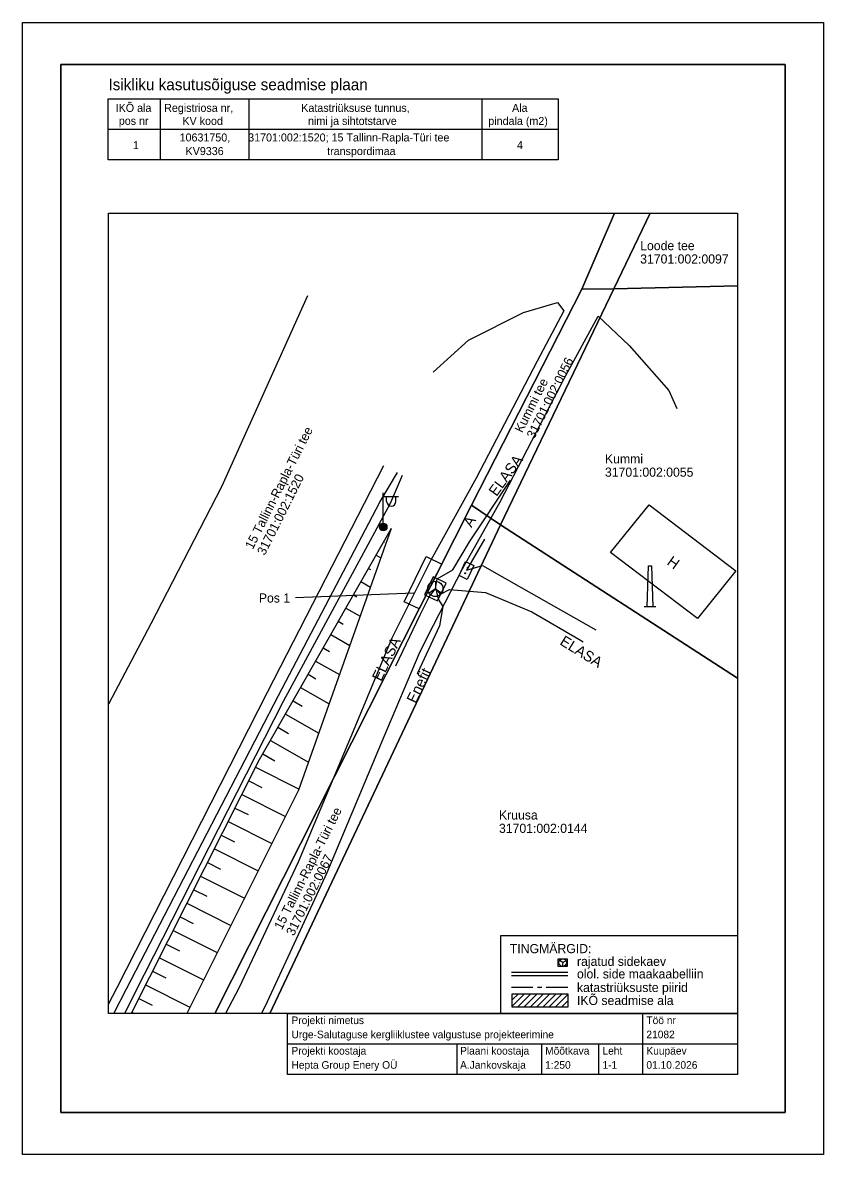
# Model space of a CAD drawing. Extents: x 544715.2 to 544767.7, y 6560571.5 to 6560645.7.
import ezdxf

# ---------------------------------------------------------------- set-up
doc = ezdxf.new("R2010")
doc.units = 0
for name, color, linetype in [('AED', 7, 'Continuous'), ('HOONE', 7, 'Continuous'), ('KASUTUSALA', 7, 'Continuous'), ('PIIR', 7, 'Continuous'), ('POST', 7, 'Continuous'), ('PR_SIDE', 7, 'Continuous'), ('RAJATIS', 7, 'Continuous'), ('RELJEEF', 7, 'Continuous'), ('SITRASS', 7, 'Continuous'), ('TEE', 7, 'Continuous'), ('VORMISTUS', 7, 'Continuous')]:
    doc.layers.add(name, color=color, linetype=linetype)

msp = doc.modelspace()

# ---------------------------------------------------------------- linework, layer by layer
at = {"layer": 'AED'}
msp.add_lwpolyline([(544721.237, 6560580.719), (544722.058, 6560582.33), (544732.034, 6560601.578), (544738.658, 6560614.261), (544739.83, 6560616.203)], dxfattribs=at)
at = {"layer": 'HOONE'}
msp.add_lwpolyline([(544762.012, 6560609.749), (544759.49, 6560606.615), (544753.802, 6560610.946), (544756.324, 6560614.08), (544762.012, 6560609.749)], dxfattribs=at)
at = {"layer": 'KASUTUSALA'}
msp.add_lwpolyline([(544742.724, 6560610.196), (544741.237, 6560607.25), (544740.271, 6560607.715), (544741.702, 6560610.688)], close=True, dxfattribs=at)
at = {"layer": 'PIIR'}
for points in [[(544727.845, 6560580.719), (544744.68, 6560614.07), (544751.91, 6560628.23), (544754.05, 6560633.219)], [(544754.05, 6560633.219), (544751.91, 6560628.23), (544754.02, 6560628.26), (544756.396, 6560633.219)], [(544756.396, 6560633.219), (544754.02, 6560628.26), (544762.123, 6560628.454)], [(544762.123, 6560628.454), (544754.02, 6560628.26), (544746.58, 6560612.78), (544762.123, 6560602.717)], [(544731.446, 6560580.719), (544746.58, 6560612.78), (544744.68, 6560614.07), (544727.845, 6560580.719)], [(544762.123, 6560602.717), (544746.58, 6560612.78), (544731.446, 6560580.719)]]:
    msp.add_lwpolyline(points, dxfattribs=at)
msp.add_lwpolyline([(544751.91, 6560628.23), (544744.68, 6560614.07), (544746.58, 6560612.78), (544754.02, 6560628.26)], close=True, dxfattribs=at)
at = {"layer": 'POST'}
for p, q in [((544738.887, 6560612.878), (544738.887, 6560614.878)), ((544738.887, 6560612.878), (544738.887, 6560614.878)), ((544738.887, 6560614.628), (544739.887, 6560614.628)), ((544738.887, 6560614.628), (544739.887, 6560614.628)), ((544739.114, 6560614.307), (544739.114, 6560614.628)), ((544739.114, 6560614.307), (544739.114, 6560614.628)), ((544739.727, 6560614.307), (544739.727, 6560614.628)), ((544739.727, 6560614.307), (544739.727, 6560614.628)), ((544738.887, 6560612.628), (544738.887, 6560612.628)), ((544738.887, 6560612.628), (544738.887, 6560612.628))]:
    msp.add_line(p, q, dxfattribs=at)
msp.add_lwpolyline([(544743.862, 6560609.452), (544744.292, 6560610.355), (544744.834, 6560610.096), (544744.403, 6560609.194)], close=True, dxfattribs=at)
for centre, radius in [((544738.887, 6560612.628), 0.25), ((544738.887, 6560612.628), 0.25), ((544738.887, 6560612.628), 0.225), ((544738.887, 6560612.628), 0.225), ((544738.887, 6560612.628), 0.2), ((544738.887, 6560612.628), 0.2), ((544738.887, 6560612.628), 0.175), ((544738.887, 6560612.628), 0.175), ((544738.887, 6560612.628), 0.15), ((544738.887, 6560612.628), 0.15), ((544738.887, 6560612.628), 0.125), ((544738.887, 6560612.628), 0.125), ((544738.887, 6560612.628), 0.1), ((544738.887, 6560612.628), 0.1), ((544738.887, 6560612.628), 0.075), ((544738.887, 6560612.628), 0.075), ((544738.887, 6560612.628), 0.05), ((544738.887, 6560612.628), 0.05), ((544738.887, 6560612.628), 0.025), ((544738.887, 6560612.628), 0.025), ((544744.434, 6560609.955), 0.0304), ((544744.434, 6560609.955), 0.029), ((544744.434, 6560609.955), 0.0277), ((544744.434, 6560609.955), 0.0263), ((544744.434, 6560609.955), 0.0249), ((544744.434, 6560609.955), 0.0236), ((544744.434, 6560609.955), 0.0222), ((544744.434, 6560609.955), 0.0209), ((544744.434, 6560609.955), 0.0195), ((544744.434, 6560609.955), 0.0181), ((544744.434, 6560609.955), 0.0168), ((544744.434, 6560609.955), 0.0154), ((544744.434, 6560609.955), 0.014), ((544744.434, 6560609.955), 0.0127), ((544744.434, 6560609.955), 0.0113), ((544744.434, 6560609.955), 0.00996), ((544744.434, 6560609.955), 0.0086), ((544744.434, 6560609.955), 0.00724), ((544744.434, 6560609.955), 0.00587), ((544744.434, 6560609.955), 0.00451), ((544744.434, 6560609.955), 0.00315), ((544744.434, 6560609.955), 0.00179), ((544744.434, 6560609.955), 0.000426), ((544744.261, 6560609.594), 0.0304), ((544744.261, 6560609.594), 0.029), ((544744.261, 6560609.594), 0.0277), ((544744.261, 6560609.594), 0.0263), ((544744.261, 6560609.594), 0.0249), ((544744.261, 6560609.594), 0.0236), ((544744.261, 6560609.594), 0.0222), ((544744.261, 6560609.594), 0.0209), ((544744.261, 6560609.594), 0.0195), ((544744.261, 6560609.594), 0.0181), ((544744.261, 6560609.594), 0.0168), ((544744.261, 6560609.594), 0.0154), ((544744.261, 6560609.594), 0.014), ((544744.261, 6560609.594), 0.0127), ((544744.261, 6560609.594), 0.0113), ((544744.261, 6560609.594), 0.00996), ((544744.261, 6560609.594), 0.0086), ((544744.261, 6560609.594), 0.00724), ((544744.261, 6560609.594), 0.00587), ((544744.261, 6560609.594), 0.00451), ((544744.261, 6560609.594), 0.00315), ((544744.261, 6560609.594), 0.00179), ((544744.261, 6560609.594), 0.000426)]:
    msp.add_circle(centre, radius, dxfattribs=at)
msp.add_arc((544739.42, 6560614.307), 0.306, 180, 0, dxfattribs=at)
msp.add_arc((544739.42, 6560614.307), 0.306, 180, 0, dxfattribs=at)
at = {"layer": 'PR_SIDE'}
for p, q in [((544742.307, 6560609.067), (544742.307, 6560608.567)), ((544742.307, 6560608.567), (544741.892, 6560608.292)), ((544742.307, 6560608.567), (544742.722, 6560608.292))]:
    msp.add_line(p, q, dxfattribs=at)
msp.add_lwpolyline([(544742.17, 6560609.354), (544741.606, 6560608.183), (544742.444, 6560607.779), (544743.008, 6560608.951)], close=True, dxfattribs=at)
msp.add_circle((544742.307, 6560608.567), 0.5, dxfattribs=at)
at = {"layer": 'RAJATIS'}
for p, q in [((544756.289, 6560610.082), (544756.482, 6560610.082)), ((544756.482, 6560610.082), (544756.578, 6560607.387)), ((544756.771, 6560607.387), (544756.001, 6560607.387)), ((544756.578, 6560607.387), (544756.193, 6560607.387))]:
    msp.add_line(p, q, dxfattribs=at)
msp.add_lwpolyline([(544756.483, 6560610.082), (544756.578, 6560607.387), (544756.193, 6560607.387), (544756.288, 6560610.082)], close=True, dxfattribs=at)
at = {"layer": 'RELJEEF'}
for p, q in [((544739.408, 6560612.523), (544739.408, 6560612.523)), ((544738.913, 6560611.654), (544738.96, 6560611.627)), ((544738.418, 6560610.785), (544738.731, 6560610.607)), ((544737.923, 6560609.916), (544738.064, 6560609.836)), ((544737.428, 6560609.047), (544738.054, 6560608.691)), ((544736.933, 6560608.178), (544737.168, 6560608.045)), ((544736.438, 6560607.309), (544737.376, 6560606.775)), ((544735.943, 6560606.441), (544736.272, 6560606.254)), ((544735.448, 6560605.572), (544736.699, 6560604.859)), ((544734.953, 6560604.703), (544735.376, 6560604.462)), ((544734.459, 6560603.834), (544736.022, 6560602.943)), ((544733.964, 6560602.965), (544734.479, 6560602.671)), ((544733.469, 6560602.096), (544735.345, 6560601.027)), ((544732.974, 6560601.227), (544733.583, 6560600.88)), ((544732.479, 6560600.358), (544734.668, 6560599.111)), ((544731.984, 6560599.489), (544732.687, 6560599.088)), ((544731.489, 6560598.62), (544733.99, 6560597.195)), ((544730.994, 6560597.751), (544731.791, 6560597.297)), ((544730.523, 6560596.87), (544733.368, 6560595.434)), ((544730.072, 6560595.977), (544730.929, 6560595.545)), ((544729.621, 6560595.084), (544732.48, 6560593.642)), ((544729.171, 6560594.191), (544730.029, 6560593.758)), ((544728.72, 6560593.299), (544731.583, 6560591.854)), ((544728.27, 6560592.406), (544729.129, 6560591.972)), ((544727.819, 6560591.513), (544730.687, 6560590.066)), ((544727.369, 6560590.621), (544728.23, 6560590.186)), ((544726.918, 6560589.728), (544729.791, 6560588.278)), ((544726.467, 6560588.835), (544727.33, 6560588.4)), ((544726.017, 6560587.942), (544728.895, 6560586.49)), ((544725.566, 6560587.05), (544726.43, 6560586.613)), ((544725.116, 6560586.157), (544727.999, 6560584.702)), ((544724.665, 6560585.264), (544725.531, 6560584.827)), ((544724.214, 6560584.371), (544727.102, 6560582.914)), ((544723.764, 6560583.479), (544724.631, 6560583.041)), ((544723.313, 6560582.586), (544726.206, 6560581.126)), ((544722.863, 6560581.693), (544723.731, 6560581.255)), ((544722.412, 6560580.8), (544722.574, 6560580.719))]:
    msp.add_line(p, q, dxfattribs=at)
for points in [[(544739.408, 6560612.523), (544730.763, 6560597.346), (544722.371, 6560580.719)], [(544739.408, 6560612.523), (544733.343, 6560595.364), (544726.002, 6560580.719)]]:
    msp.add_lwpolyline(points, dxfattribs=at)
at = {"layer": 'SITRASS'}
for points in [[(544742.307, 6560608.567), (544742.434, 6560609.227), (544743.461, 6560609.821), (544744.546, 6560611.657), (544747.243, 6560615.692)], [(544745.52, 6560611.834), (544744.357, 6560609.803)], [(544744.357, 6560609.803), (544745.392, 6560610.113)], [(544745.392, 6560610.113), (544747.929, 6560608.662), (544752.831, 6560605.879)], [(544739.725, 6560603.511), (544741.31, 6560606.868), (544741.895, 6560608.043), (544742.307, 6560608.567)], [(544742.332, 6560608.578), (544742.496, 6560607.887), (544742.79, 6560607.42), (544742.588, 6560606.141), (544741.145, 6560603.047), (544741.116, 6560602.984)], [(544742.307, 6560608.567), (544742.653, 6560608.213), (544743.225, 6560608.535), (544745.595, 6560608.342), (544748.643, 6560607.071), (544751.717, 6560605.277), (544751.991, 6560605.105)]]:
    msp.add_lwpolyline(points, dxfattribs=at)
at = {"layer": 'TEE'}
for points in [[(544733.934, 6560627.793), (544728.292, 6560615.274), (544723.65, 6560606.272), (544720.873, 6560601)], [(544742.172, 6560622.797), (544744.481, 6560624.88), (544748.08, 6560626.694), (544750.321, 6560627.366), (544750.73, 6560626.821), (544748.985, 6560623.517), (544744.977, 6560615.832), (544742.015, 6560610.453), (544739.455, 6560605.333)], [(544741.302, 6560604.463), (544742.186, 6560606.186), (544744.086, 6560609.876), (544746.564, 6560614.282), (544750.732, 6560622.318), (544752.987, 6560626.468), (544755.012, 6560624.539), (544757.625, 6560621.575), (544758.142, 6560620.402)], [(544720.873, 6560581.313), (544721.449, 6560582.414), (544731.292, 6560601.787), (544738.927, 6560616.655)], [(544721.953, 6560580.719), (544722.619, 6560582.079), (544732.346, 6560601.2), (544739.356, 6560614.182), (544740.163, 6560616.037)], [(544739.455, 6560605.333), (544737.024, 6560599.505), (544733.309, 6560590.648), (544729.425, 6560582.362), (544728.556, 6560580.719)], [(544730.916, 6560580.719), (544731.178, 6560581.223), (544735.213, 6560589.953), (544738.884, 6560598.739), (544741.302, 6560604.463)]]:
    msp.add_lwpolyline(points, dxfattribs=at)
at = {"layer": 'VORMISTUS'}
for p, q in [((544724.259, 6560640.724), (544724.259, 6560636.724)), ((544730.084, 6560640.724), (544730.084, 6560636.724)), ((544745.359, 6560640.724), (544745.359, 6560636.724)), ((544720.859, 6560638.724), (544750.359, 6560638.724)), ((544740.906, 6560608.294), (544733.134, 6560607.973)), ((544750.658, 6560584.05), (544750.444, 6560584.178)), ((544750.658, 6560584.05), (544750.624, 6560583.804)), ((544750.884, 6560584.159), (544750.658, 6560584.05)), ((544747.298, 6560583.422), (544750.993, 6560583.422)), ((544747.298, 6560583.201), (544750.993, 6560583.201)), ((544748.708, 6560582.419), (544747.298, 6560582.419)), ((544749.291, 6560582.419), (544749, 6560582.419)), ((544750.993, 6560582.419), (544749.582, 6560582.419)), ((544748.162, 6560582.006), (544747.352, 6560581.196)), ((544747.75, 6560582.006), (544747.352, 6560581.608)), ((544748.573, 6560582.006), (544747.7, 6560581.132)), ((544748.985, 6560582.006), (544748.112, 6560581.132)), ((544749.397, 6560582.006), (544748.524, 6560581.132)), ((544749.809, 6560582.006), (544748.935, 6560581.132)), ((544750.221, 6560582.006), (544749.347, 6560581.132)), ((544750.633, 6560582.006), (544749.759, 6560581.132)), ((544750.993, 6560581.954), (544750.171, 6560581.132)), ((544750.993, 6560581.542), (544750.583, 6560581.132)), ((544755.896, 6560580.719), (544755.896, 6560578.719)), ((544732.623, 6560578.719), (544762.123, 6560578.719)), ((544743.716, 6560578.719), (544743.716, 6560576.719)), ((544749.259, 6560578.719), (544749.259, 6560576.719)), ((544753.012, 6560578.719), (544753.012, 6560576.719)), ((544755.896, 6560578.719), (544755.896, 6560576.719))]:
    msp.add_line(p, q, dxfattribs=at)
for points in [[(544715.248, 6560645.719), (544767.748, 6560645.719), (544767.748, 6560571.469), (544715.248, 6560571.469)], [(544717.748, 6560574.219), (544765.248, 6560574.219), (544765.248, 6560642.969), (544717.748, 6560642.969)], [(544717.748, 6560642.969), (544765.248, 6560642.969), (544765.248, 6560574.219), (544717.748, 6560574.219)], [(544720.859, 6560640.724), (544750.359, 6560640.724), (544750.359, 6560636.724), (544720.859, 6560636.724)], [(544762.123, 6560580.719), (544720.873, 6560580.719), (544720.873, 6560633.219), (544762.123, 6560633.219)], [(544746.593, 6560580.719), (544746.593, 6560585.819), (544762.123, 6560585.819), (544762.123, 6560580.719)], [(544750.983, 6560584.283), (544750.333, 6560584.283), (544750.333, 6560583.818), (544750.983, 6560583.818)], [(544747.352, 6560582.006), (544750.993, 6560582.006), (544750.993, 6560581.132), (544747.352, 6560581.132)], [(544732.623, 6560580.719), (544762.123, 6560580.719), (544762.123, 6560576.719), (544732.623, 6560576.719)]]:
    msp.add_lwpolyline(points, close=True, dxfattribs=at)
msp.add_circle((544750.658, 6560584.05), 0.25, dxfattribs=at)

# ---------------------------------------------------------------- texts
at = {"layer": 'HOONE'}
msp.add_text('H', height=0.7, rotation=324.36519, dxfattribs=at).set_placement((544757.439, 6560610.208))
at = {"layer": 'PIIR'}
for s, p in [('Loode tee', (544755.738, 6560630.788)), ('31701:002:0097', (544755.738, 6560629.913)), ('Kummi', (544753.428, 6560616.802)), ('31701:002:0055', (544753.428, 6560615.927)), ('Kruusa', (544746.479, 6560593.435)), ('31701:002:0144', (544746.479, 6560592.56))]:
    msp.add_text(s, height=0.6, dxfattribs=at).set_placement(p)
for s, rotation, p in [('31701:002:0056', 63.46115, (544748.794, 6560618.373)), ('Kummi tee', 63.46115, (544748.011, 6560618.764)), ('15 Tallinn-Rapla-Türi tee', 63.36779, (544730.337, 6560611.118)), ('31701:002:1520', 63.36779, (544731.12, 6560610.725)), ('15 Tallinn-Rapla-Türi tee', 63.43301, (544732.243, 6560586.153)), ('31701:002:0067', 63.43301, (544733.025, 6560585.761))]:
    msp.add_text(s, height=0.6, rotation=rotation, dxfattribs=at).set_placement(p)
at = {"layer": 'SITRASS'}
for s, rotation, p in [('ELASA', 53.97635, (544746.316, 6560614.593)), ('ELASA', 328.24149, (544750.414, 6560604.953)), ('ELASA', 64.23226, (544738.753, 6560602.459)), ('Enefit', 64.23226, (544741.022, 6560601.004))]:
    msp.add_text(s, height=0.7, rotation=rotation, dxfattribs=at).set_placement(p)
at = {"layer": 'TEE'}
msp.add_text('A', height=0.7, rotation=59.20555, dxfattribs=at).set_placement((544744.677, 6560612.548))
at = {"layer": 'VORMISTUS'}
for s, height, p in [('Isikliku kasutusõiguse seadmise plaan', 0.75, (544720.875, 6560641.286)), ('IKÕ ala', 0.525, (544721.348, 6560639.864)), ('Registriosa nr,', 0.525, (544724.527, 6560639.864)), ('Katastriüksuse tunnus,', 0.525, (544733.517, 6560639.864)), ('Ala', 0.525, (544747.338, 6560639.864)), ('pos nr', 0.525, (544721.553, 6560639.013)), ('KV kood', 0.525, (544725.724, 6560639.006)), ('nimi ja sihtotstarve', 0.525, (544733.962, 6560639.009)), ('pindala (m2)', 0.525, (544745.782, 6560639.006)), ('1', 0.525, (544722.484, 6560637.424)), ('10631750,', 0.525, (544725.539, 6560637.924)), ('31701:002:1520; 15 Tallinn-Rapla-Türi tee', 0.525, (544730.036, 6560637.924)), ('4', 0.525, (544747.658, 6560637.424)), ('KV9336', 0.525, (544725.93, 6560637.03)), ('transpordimaa', 0.525, (544735.213, 6560637.03)), ('Pos 1', 0.6, (544730.734, 6560607.673)), ('TINGMÄRGID:', 0.6, (544747.193, 6560584.669)), ('rajatud sidekaev', 0.6, (544751.593, 6560583.832)), ('olol. side maakaabelliin', 0.6, (544751.593, 6560583.011)), ('katastriüksuste piirid', 0.6, (544751.593, 6560582.119)), ('IKÕ seadmise ala', 0.6, (544751.593, 6560581.269)), ('Projekti nimetus', 0.5, (544732.872, 6560580.015)), ('Töö nr', 0.5, (544756.145, 6560580.015)), ('Urge-Salutaguse kergliiklustee valgustuse projekteerimine', 0.5, (544732.872, 6560579.086)), ('21082', 0.5, (544756.145, 6560579.086)), ('Projekti koostaja', 0.5, (544732.872, 6560578.015)), ('Plaani koostaja', 0.5, (544743.929, 6560578.015)), ('Mõõtkava', 0.5, (544749.508, 6560578.015)), ('Leht', 0.5, (544753.261, 6560578.015)), ('Kuupäev', 0.5, (544756.145, 6560578.015)), ('Hepta Group Enery OÜ', 0.5, (544732.872, 6560577.086)), ('A.Jankovskaja', 0.5, (544743.929, 6560577.086)), ('1:250', 0.5, (544749.508, 6560577.086)), ('1-1', 0.5, (544753.261, 6560577.086)), ('01.10.2026', 0.5, (544756.145, 6560577.086))]:
    msp.add_text(s, height=height, dxfattribs=at).set_placement(p)

doc.saveas('drawing.dxf')
